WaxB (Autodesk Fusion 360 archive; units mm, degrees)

design "Wax Part B" references "HappyRing v7 v8_Part B Bottom", "HappyRing v7 Wax Mold Positive A"
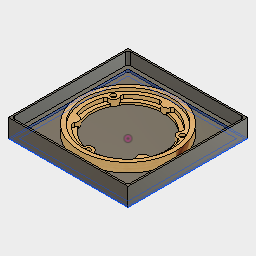
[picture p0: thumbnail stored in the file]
component_insert "Component Insert1"
component_insert "Component Insert3"
joint "Assemble2" OffsetX 0 OffsetY 0 OffsetZ 0 AngleZ 0 OffsetX 0 OffsetY 0 OffsetZ 0 AngleZ 0 alignAngle 0 alignOffsetX 0 alignOffsetY 0 alignOffsetZ 0

design "HappyRing v7 v8_Part B Bottom"
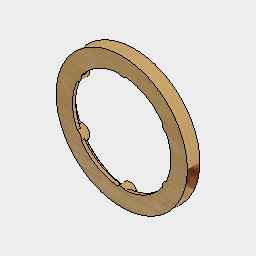
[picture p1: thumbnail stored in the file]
base_feature "Base Feature" bodies "Part B Bottom"
named bodies: "Part B Bottom"

design "HappyRing v7 Wax Mold Positive A"
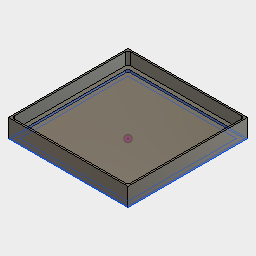
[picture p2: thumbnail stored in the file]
parameter "height" = 23 comment "height of the component"
parameter "rail_height" = 3
parameter "exrtusion_delta_for_magnets" = 0.8
parameter "diameter" = 130
parameter "inner_diameter" = 110
parameter "diameter_offet" = 10
parameter "pressfit_offset" = 1
parameter "magnet_diameter" = 6.4
parameter "magnet_height" = 3.2
parameter "holes_position_from_diameter" = 20
parameter "plateform_height" = 5.75 (= "height / 4")
parameter "plateform_inner_diameter" = 100
parameter "tool_diameter" = 3
sketch "base" plane through (0, 0, 0) normal (0, 1, 0) x axis (1, 0, 0)
  line L1 (68, -68) -> (-68, -68)
  line L2 (68, 68) -> (68, -68)
  line L3 (-68, 68) -> (68, 68)
  line L4 (-68, -68) -> (-68, 68)
  line L5 (-73, 73) -> (73, 73)
  line L6 (-73, -73) -> (-73, 73)
  line L7 (73, -73) -> (-73, -73)
  line L8 (73, 73) -> (73, -73)
  line L9 (75, 75) -> (75, -75)
  line L10 (-75, 75) -> (75, 75)
  line L11 (-75, -75) -> (-75, 75)
  line L12 (75, -75) -> (-75, -75)
  point P2 (-68, -68)
  point P3 (68, -68)
  point P5 (-68, 68)
  point P1 (0, 0)
  dimension "d138" distance P2 P3 = 136 (= "diameter + 2 * tool_diameter")
  dimension "d139" distance P2 P5 = 136 (= "diameter + 2 * tool_diameter")
  dimension "d143" = 5
  dimension "d144" = 7
  dimension "d153" distance P1 L11 = 75
  dimension "d154" distance P1 L10 = 75
extrude "Extrude20" new body sketch "base" profile of L5 L7 L6 L8 L9 L10 L12 L11 along normal blind 23 (= "height")
extrude "Extrude21" new body sketch "base" profile of L1 L2 L3 L4 along normal blind 5
extrude "Extrude22" add sketch "base" profile of L1 L2 L3 L4 L5 L7 L6 L8 along normal blind 7.8 (= "rail_height + 5 mm - 0.2 mm")
fillet "Fillet4" radius 3 (= "tool_diameter")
